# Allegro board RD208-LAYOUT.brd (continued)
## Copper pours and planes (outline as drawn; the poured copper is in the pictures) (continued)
PC_G_V8 on TOP (solid shape): 157.26,98.82 157.8,99.02 158.92,98.73 159.3,98.25 158.92,97.77 157.8,97.48 157.74,97.46 157.68,97.46 157.23,97.73 157.27,98.25
PC_G_V8 on TOP: 157.65,87.35 157.53,87.38 157.43,87.47 157.4,87.6 157.4,90.3 157.43,90.42 157.53,90.52 157.65,90.55 158.65,90.55 158.78,90.58 158.87,90.67 158.9,90.8 158.9,98.55 158.93,98.67 159.03,98.77 159.15,98.8 162.35,98.8 162.46,98.76 162.5,98.65 162.5,87.6 162.47,87.47 162.38,87.38 162.25,87.35
PC_G_W1 on TOP (solid shape): 196.08,75.6 196.5,75.6 196.5,75.2 196.08,75.2 196.08,71.67 195.23,71.67 195.23,72.72 194.81,72.72 194.81,71.67 193.96,71.67 193.96,72.72 193.54,72.72 193.54,71.67 192.69,71.67 192.69,72.72 192.27,72.72 192.27,71.67 191.42,71.67 191.42,75.2 191,75.2 191,75.6 191.42,75.6 191.42,76.47 196.08,76.47
PC_G_W1 on TOP (solid shape): 186.2,69.6 186.35,69.25 186.33,69.12 186.28,68.99 185.69,67.99 185.17,67.76 184.77,68.17 184.36,68.57 184.59,69.09 185.72,69.73 185.85,69.75
PC_G_W1 on TOP: 199.3,65.5 199.24,65.51 199.13,65.57 196.57,68.13 196.46,68.19 196.4,68.2 192.95,68.2 192.82,68.23 192.73,68.33 192.7,68.45 192.7,69.38 192.67,69.5 192.57,69.59 192.45,69.62 191.75,69.62 191.64,69.67 191.6,69.78 191.6,76.2 191.63,76.33 191.72,76.42 191.85,76.45 195.8,76.45 195.86,76.44 195.97,76.38 199.41,72.94 199.44,72.9 199.45,72.84 199.45,72.55 199.52,72.37 199.7,72.3 203.85,72.3 203.96,72.26 204,72.15 204,65.65 203.96,65.54 203.85,65.5
PC_G_W2 on TOP (solid shape): 196.08,84.85 196.5,84.85 196.5,84.45 196.08,84.45 196.08,80.92 195.23,80.92 195.23,81.97 194.81,81.97 194.81,80.92 193.96,80.92 193.96,81.97 193.54,81.97 193.54,80.92 192.69,80.92 192.69,81.97 192.27,81.97 192.27,80.92 191.42,80.92 191.42,84.45 191,84.45 191,84.85 191.42,84.85 191.42,85.72 196.08,85.72
PC_G_W2 on TOP (solid shape): 186.2,78.85 186.35,78.5 186.33,78.37 186.28,78.24 185.69,77.24 185.17,77.01 184.77,77.42 184.36,77.82 184.59,78.34 185.72,78.98 185.85,79
PC_G_W2 on TOP: 198.7,76.25 198.64,76.26 198.53,76.32 197.47,77.38 197.36,77.44 197.3,77.45 192.95,77.45 192.82,77.48 192.73,77.58 192.7,77.7 192.7,78.62 192.67,78.75 192.57,78.84 192.45,78.88 191.75,78.88 191.64,78.92 191.6,79.03 191.6,85.45 191.63,85.58 191.72,85.67 191.85,85.7 195.8,85.7 195.86,85.69 195.97,85.63 196,85.6 198.25,85.6 198.31,85.59 198.42,85.53 199.38,84.57 199.42,84.52 199.45,84.4 199.45,83.3 199.52,83.12 199.7,83.05 203.85,83.05 203.96,83.01 204,82.9 204,76.4 203.96,76.29 203.85,76.25
PC_G_W3 on TOP (solid shape): 196.08,94.1 196.5,94.1 196.5,93.7 196.08,93.7 196.08,90.17 195.23,90.17 195.23,91.22 194.81,91.22 194.81,90.17 193.96,90.17 193.96,91.22 193.54,91.22 193.54,90.17 192.69,90.17 192.69,91.22 192.27,91.22 192.27,90.17 191.42,90.17 191.42,93.7 191,93.7 191,94.1 191.42,94.1 191.42,94.97 196.08,94.97
PC_G_W3 on TOP (solid shape): 186.2,88.1 186.35,87.75 186.33,87.62 186.28,87.49 185.69,86.49 185.17,86.26 184.77,86.67 184.36,87.07 184.59,87.59 185.72,88.23 185.85,88.25
PC_G_W3 on TOP: 192.95,86.7 192.82,86.73 192.73,86.83 192.7,86.95 192.7,87.88 192.67,88 192.57,88.09 192.45,88.12 191.75,88.12 191.64,88.17 191.6,88.28 191.6,94.7 191.63,94.83 191.72,94.92 191.85,94.95 195.65,94.95 195.78,94.92 195.87,94.83 195.9,94.7 195.9,94.05 195.93,93.92 196.03,93.83 196.15,93.8 203.85,93.8 203.96,93.76 204,93.65 204,87.15 203.96,87.04 203.85,87 196.1,87 195.95,86.95 195.8,86.73 195.71,86.7
PC_G_W5 on TOP (solid shape): 196.08,116.2 196.5,116.2 196.5,115.8 196.08,115.8 196.08,112.28 195.23,112.28 195.23,113.33 194.81,113.33 194.81,112.28 193.96,112.28 193.96,113.33 193.54,113.33 193.54,112.28 192.69,112.28 192.69,113.33 192.27,113.33 192.27,112.28 191.42,112.28 191.42,115.8 191,115.8 191,116.2 191.42,116.2 191.42,117.08 196.08,117.08
PC_G_W5 on TOP (solid shape): 186.2,110.2 186.35,109.85 186.33,109.72 186.28,109.59 185.69,108.59 185.17,108.36 184.77,108.77 184.36,109.17 184.59,109.69 185.72,110.33 185.85,110.35
PC_G_W5 on TOP: 196.95,108.4 196.89,108.41 196.78,108.47 196.52,108.73 196.41,108.79 196.35,108.8 192.95,108.8 192.82,108.83 192.73,108.92 192.7,109.05 192.7,109.97 192.67,110.1 192.57,110.19 192.45,110.22 191.75,110.22 191.64,110.27 191.6,110.38 191.6,116.8 191.63,116.92 191.72,117.02 191.85,117.05 199,117.05 199.12,117.02 199.22,116.92 199.25,116.8 199.25,112.45 199.34,112.24 199.55,112.15 200.2,112.15 200.31,112.11 200.35,112 200.35,108.65 200.32,108.53 200.22,108.43 200.1,108.4
PC_G_W6 on TOP (solid shape): 196.08,125.45 196.5,125.45 196.5,125.05 196.08,125.05 196.08,121.53 195.23,121.53 195.23,122.58 194.81,122.58 194.81,121.53 193.96,121.53 193.96,122.58 193.54,122.58 193.54,121.53 192.69,121.53 192.69,122.58 192.27,122.58 192.27,121.53 191.42,121.53 191.42,125.05 191,125.05 191,125.45 191.42,125.45 191.42,126.33 196.08,126.33
PC_G_W6 on TOP (solid shape): 186.2,119.45 186.35,119.1 186.33,118.97 186.28,118.84 185.69,117.84 185.17,117.61 184.77,118.02 184.36,118.42 184.59,118.94 185.72,119.58 185.85,119.6
PC_G_W6 on TOP: 192.95,118.05 192.82,118.08 192.73,118.17 192.7,118.3 192.7,119.22 192.67,119.35 192.57,119.44 192.45,119.47 191.75,119.47 191.64,119.52 191.6,119.62 191.6,126.05 191.63,126.17 191.72,126.27 191.85,126.3 199,126.3 199.12,126.27 199.22,126.17 199.25,126.05 199.25,123.2 199.34,122.99 199.55,122.9 200.2,122.9 200.31,122.86 200.35,122.75 200.35,118.3 200.32,118.17 200.22,118.08 200.1,118.05
PC_G_W7 on TOP (solid shape): 196.08,134.7 196.5,134.7 196.5,134.3 196.08,134.3 196.08,130.78 195.23,130.78 195.23,131.82 194.81,131.82 194.81,130.78 193.96,130.78 193.96,131.82 193.54,131.82 193.54,130.78 192.69,130.78 192.69,131.82 192.27,131.82 192.27,130.78 191.42,130.78 191.42,134.3 191,134.3 191,134.7 191.42,134.7 191.42,135.57 196.08,135.57
PC_G_W7 on TOP (solid shape): 186.2,128.7 186.35,128.35 186.33,128.22 186.28,128.09 185.69,127.09 185.17,126.86 184.77,127.27 184.36,127.67 184.59,128.19 185.72,128.83 185.85,128.85
PC_G_W7 on TOP: 192.95,127.3 192.82,127.33 192.73,127.42 192.7,127.55 192.7,128.5 192.67,128.62 192.57,128.72 192.45,128.75 191.85,128.75 191.72,128.78 191.63,128.88 191.6,129 191.6,135.3 191.63,135.43 191.72,135.52 191.85,135.55 199,135.55 199.12,135.52 199.22,135.43 199.25,135.3 199.25,133.95 199.34,133.74 199.55,133.65 200.2,133.65 200.31,133.61 200.35,133.5 200.35,130.05 200.31,129.94 200.2,129.9 199.2,129.9 199.08,129.87 199.03,129.83 196.57,127.37 196.52,127.33 196.4,127.3
PC_G_W8 on TOP (solid shape): 185.31,138.35 185.48,138.07 185.77,136.95 185.57,136.41 185,136.42 184.43,136.41 184.23,136.95 184.52,138.07 184.69,138.35 185,138.45
PC_G_W8 on TOP: 193.15,136.55 193.03,136.58 192.93,136.68 192.9,136.8 192.9,137.8 192.87,137.93 192.78,138.02 192.65,138.05 184.7,138.05 184.57,138.08 184.48,138.18 184.45,138.3 184.45,141.5 184.49,141.61 184.6,141.65 195.65,141.65 195.78,141.62 195.87,141.53 195.9,141.4 195.9,136.8 195.87,136.68 195.78,136.58 195.65,136.55
TRANS2_AUX on BOTTOM (solid shape): 197.03,10.28 197.5,10.6 197.97,10.28 198.52,8.85 198.24,8.2 197.59,8.49 197.58,8.53 197.42,8.53 197.41,8.49 196.76,8.2 196.48,8.85
TRANS2_PRI on BOTTOM (solid shape): 188.82,17.45 189.25,17.45 189.25,17.05 188.82,17.05 188.82,15.8 188.68,15.8 188.68,15.5 188.28,15.5 188.28,15.8 188.03,15.8 188.03,15.5 187.62,15.5 187.62,15.8 187.38,15.8 187.38,15.5 186.97,15.5 186.97,15.8 186.72,15.8 186.72,15.5 186.32,15.5 186.32,15.8 186.18,15.8 186.18,17.05 185.75,17.05 185.75,17.45 186.18,17.45 186.18,18 188.82,18
TRANS2_PRI on BOTTOM: 187.1,7.25 187.04,7.26 186.93,7.32 186.32,7.93 186.28,7.98 186.25,8.1 186.25,17.75 186.28,17.88 186.38,17.97 186.5,18 188.5,18 188.62,17.97 188.72,17.88 188.75,17.75 188.75,8.1 188.74,8.04 188.68,7.93 188.07,7.32 188.02,7.28 187.9,7.25
TRANS2_SEC2 on BOTTOM (solid shape): 202.41,39.8 202.55,39.45 202.52,39.27 202.43,39.12 202.4,39.08 202.47,38.95 202.51,38.95 203.06,38.5 202.61,37.96 201.08,37.8 200.58,38.07 200.66,38.63 201.68,39.78 201.85,39.9 202.05,39.95
TRANS2_SEC3 on BOTTOM (solid shape): 217.41,39.8 217.55,39.45 217.52,39.27 217.43,39.12 217.4,39.08 217.47,38.95 217.51,38.95 218.06,38.5 217.61,37.96 216.08,37.8 215.58,38.07 215.66,38.63 216.68,39.78 216.85,39.9 217.05,39.95
TRANS2_SEC4 on BOTTOM (solid shape): 217.03,10.28 217.5,10.6 217.97,10.28 218.52,8.85 218.24,8.2 217.59,8.49 217.58,8.53 217.42,8.53 217.41,8.49 216.76,8.2 216.48,8.85
V_UL on TOP (solid shape): 48.77,99.08 49.19,99.08 49.19,100.12 50.04,100.12 50.04,99.08 50.46,99.08 50.46,100.12 51.31,100.12 51.31,99.08 51.73,99.08 51.73,100.12 52.58,100.12 52.58,96.6 53.01,96.6 53.01,96.2 52.58,96.2 52.58,95.33 47.92,95.33 47.92,96.2 47.49,96.2 47.49,96.6 47.92,96.6 47.92,100.12 48.77,100.12
V_UL on TOP (solid shape): 59.06,107.53 59.23,107.23 59.64,106.83 59.41,106.31 58.41,105.72 57.8,105.8 57.72,106.41 58.31,107.41 58.49,107.59 58.74,107.65
V_UL on BOTTOM (solid shape): 190.88,40.02 190.98,40.57 191.53,40.67 192.94,40.06 193.16,39.87 193.24,39.6 193.09,39.25 192.74,39.1 192.64,39.11 192.54,39.14 192.5,39.16 192.39,39.05 192.41,39.01 192.15,38.35 191.49,38.61
V_UL on TOP: 48.35,95.35 48.23,95.38 48.13,95.47 48.1,95.6 48.1,95.65 48.1,95.7 48.1,98.5 48.06,98.62 47.97,98.72 47.85,98.75 39.35,98.75 39.23,98.78 39.13,98.88 39.1,99 39.1,105.9 39.13,106.03 39.23,106.12 39.35,106.15 47.9,106.15 48.02,106.18 48.12,106.28 48.15,106.4 48.15,106.95 48.18,107.08 48.27,107.17 48.4,107.2 51.05,107.2 51.17,107.17 51.27,107.08 51.3,106.95 51.3,106 51.33,105.88 51.42,105.78 51.55,105.75 52.15,105.75 52.27,105.72 52.37,105.62 52.4,105.5 52.4,95.6 52.37,95.47 52.27,95.38 52.15,95.35
V_VL on TOP (solid shape): 127.8,91.83 128.68,91.83 128.68,87.17 127.8,87.17 127.8,86.75 127.4,86.75 127.4,87.17 123.88,87.17 123.88,88.02 124.92,88.02 124.92,88.44 123.88,88.44 123.88,89.29 124.92,89.29 124.92,89.71 123.88,89.71 123.88,90.56 124.92,90.56 124.92,90.98 123.88,90.98 123.88,91.83 127.4,91.83 127.4,92.25 127.8,92.25
V_VL on TOP (solid shape): 117.17,98.89 117.69,98.66 118.33,97.53 118.35,97.4 118.2,97.05 117.85,96.9 117.72,96.92 117.59,96.97 116.59,97.56 116.36,98.08 116.77,98.48
V_VL on BOTTOM (solid shape): 207.03,40.88 207.5,41.2 207.97,40.88 208.52,39.45 208.24,38.8 207.59,39.09 207.58,39.13 207.42,39.13 207.41,39.09 206.76,38.8 206.48,39.45
V_VL on TOP: 118.1,78.25 117.97,78.28 117.88,78.38 117.85,78.5 117.85,86.95 117.82,87.08 117.72,87.17 117.6,87.2 117.05,87.2 116.92,87.23 116.83,87.33 116.8,87.45 116.8,90.3 116.83,90.42 116.92,90.52 117.05,90.55 117.97,90.55 118.1,90.58 118.19,90.67 118.22,90.8 118.22,91.5 118.27,91.61 118.38,91.65 128.4,91.65 128.53,91.62 128.62,91.53 128.65,91.4 128.65,87.6 128.62,87.47 128.53,87.38 128.4,87.35 128.3,87.35 126.5,87.35 126.38,87.31 126.28,87.22 126.25,87.1 126.25,79.35 126.24,79.29 126.18,79.18 125.32,78.32 125.27,78.28 125.15,78.25
V_WL on TOP (solid shape): 196.08,106.95 196.5,106.95 196.5,106.55 196.08,106.55 196.08,103.03 195.23,103.03 195.23,104.08 194.81,104.08 194.81,103.03 193.96,103.03 193.96,104.08 193.54,104.08 193.54,103.03 192.69,103.03 192.69,104.08 192.27,104.08 192.27,103.03 191.42,103.03 191.42,106.55 191,106.55 191,106.95 191.42,106.95 191.42,107.83 196.08,107.83
V_WL on TOP (solid shape): 186.2,97.35 186.35,97 186.33,96.87 186.28,96.74 185.69,95.74 185.17,95.51 184.77,95.92 184.36,96.32 184.59,96.84 185.72,97.48 185.85,97.5
V_WL on BOTTOM (solid shape): 222.03,40.88 222.5,41.2 222.97,40.88 223.52,39.45 223.24,38.8 222.59,39.09 222.58,39.13 222.42,39.13 222.41,39.09 221.76,38.8 221.48,39.45
V_WL on TOP: 192.95,95.95 192.82,95.98 192.73,96.08 192.7,96.2 192.7,97.12 192.67,97.25 192.57,97.34 192.45,97.38 191.75,97.38 191.64,97.42 191.6,97.53 191.6,107.55 191.63,107.67 191.72,107.77 191.85,107.8 195.65,107.8 195.78,107.77 195.87,107.67 195.9,107.55 195.9,107.45 195.9,105.5 195.94,105.38 196.03,105.28 196.15,105.25 201.5,105.25 201.56,105.24 201.67,105.18 202.38,104.47 202.49,104.41 202.55,104.4 204.5,104.4 204.62,104.37 204.72,104.28 204.75,104.15 204.75,97.25 204.72,97.12 204.62,97.03 204.5,97 196.2,97 196.07,96.97 195.98,96.88 195.95,96.75 195.95,96.2 195.92,96.08 195.82,95.98 195.7,95.95
VP_1R8_CPLD_D on TOP (solid shape): 82.77,117.33 82.89,117.05 82.85,116.89 82.75,116.75 83.17,116.37 82.79,115.95 81.66,115.9 81.27,116.15 81.37,116.6 82.22,117.35 82.34,117.42 82.48,117.45
VP_1R8_CPLD_D on CONDUCTIVE3 (solid shape): 82.92,117.39 83.44,117.16 84.08,116.03 84.1,115.9 83.95,115.55 83.6,115.4 83.47,115.42 83.34,115.47 82.34,116.06 82.11,116.58 82.52,116.98
VP_3R3_PRH_D on TOP (solid shape): 92.27,117.33 92.39,117.05 92.35,116.89 92.25,116.75 92.67,116.37 92.29,115.95 91.16,115.9 90.77,116.15 90.87,116.6 91.72,117.35 91.84,117.42 91.98,117.45
VP_3R3_PRH_D on CONDUCTIVE4 (solid shape): 91.91,117.32 92.45,117.52 93.58,117.23 93.95,116.75 93.57,116.27 92.45,115.98 92.39,115.96 92.33,115.96 91.88,116.23 91.92,116.75
VP_3R3_PRH_D on CONDUCTIVE4 (solid shape): 92.56,118.35 92.73,118.08 93.02,116.95 92.82,116.41 92.25,116.42 91.68,116.41 91.48,116.95 91.77,118.08 91.94,118.35 92.25,118.45
VP_3R3_PRH_D on CONDUCTIVE4: 108.7,115.85 108.63,115.88 108.6,115.95 108.6,117.3 108.59,117.38 108.57,117.46 108.53,117.54 108.48,117.62 108.42,117.68 108.34,117.73 108.26,117.77 108.18,117.79 108.1,117.8 107.8,117.8 107.73,117.83 107.7,117.9 107.7,118.3 107.73,118.42 107.83,118.52 107.95,118.55 108.92,118.55 108.95,118.54 108.99,118.52 110.51,117 110.73,116.87 110.86,116.85 111.2,116.85 111.27,116.82 111.3,116.75 111.3,116.1 111.27,115.97 111.17,115.88 111.05,115.85
VP_5R0_PRH_D on CONDUCTIVE3 (solid shape): 76.81,123.16 77.33,123.39 77.73,122.98 78.14,122.58 77.91,122.06 76.91,121.47 76.3,121.55 76.22,122.16
VP_5R0_PRH_D on CONDUCTIVE3 (solid shape): 77.16,123.32 77.7,123.52 78.82,123.23 79.2,122.75 78.82,122.27 77.7,121.98 77.64,121.96 77.58,121.96 77.13,122.23 77.17,122.75
VP_5R0_PRH_D on TOP: 77.65,121.95 77.54,121.99 77.5,122.1 77.5,123.4 77.54,123.51 77.65,123.55 78,123.55 78.3,123.85 78.3,125.25 78.33,125.38 78.42,125.47 78.55,125.5 78.95,125.5 79.08,125.47 79.17,125.38 79.2,125.25 79.2,124.15 79.23,124.03 79.27,123.98 79.43,123.82 79.47,123.77 79.5,123.65 79.5,122.1 79.46,121.99 79.35,121.95
VP_15R0_INV_ISO on BOTTOM: 170.75,30.25 170.62,30.28 170.53,30.38 170.5,30.5 170.5,36.25 170.53,36.38 170.62,36.47 170.75,36.5 172.25,36.5 172.38,36.47 172.47,36.38 172.5,36.25 172.5,30.5 172.47,30.38 172.38,30.28 172.25,30.25
VP_15R0_INV_ISO on BOTTOM: 178.5,3 178.12,3.08 177.79,3.29 176.79,4.29 176.79,5.71 178.21,5.71 178.91,5 191.15,5 191.5,5.35 191.5,8.45 192.5,9.45 193.5,8.45 193.5,3.49 193.49,3.45 193.47,3.42 193.08,3.03 193.05,3.01 193.01,3
VP_15R0_INV_LDO on TOP: 149.15,33.7 149.09,33.71 148.98,33.77 148.57,34.18 148.53,34.23 148.5,34.35 148.5,34.9 148.51,34.96 148.57,35.07 149.68,36.18 149.73,36.22 149.85,36.25 152.85,36.25 152.97,36.22 153.07,36.12 153.1,36 153.1,35.3 153.07,35.17 152.97,35.08 152.85,35.05 150.85,35.05 150.73,35.02 150.68,34.98 150.57,34.87 150.51,34.76 150.5,34.7 150.5,34.35 150.49,34.29 150.43,34.18 150.02,33.77 149.97,33.73 149.85,33.7
VP_15R0_INV_LDO on BOTTOM: 101.5,8 101.38,8.03 101.28,8.12 101.25,8.25 101.25,16.25 101.28,16.38 101.38,16.47 101.5,16.5 115.65,16.5 115.78,16.47 115.87,16.38 115.9,16.25 115.9,9.61 115.89,9.55 115.86,9.51 114.39,8.04 114.35,8.01 114.29,8
VP_15R0_INV_LDO on BOTTOM: 165,30 164.88,30.03 164.78,30.12 164.75,30.25 164.75,32.4 164.76,32.46 164.82,32.57 165.18,32.93 165.23,32.97 165.35,33 166.5,33 166.62,32.97 166.72,32.88 166.75,32.75 166.75,30.25 166.72,30.12 166.62,30.03 166.5,30
VP_400R0_INV on TOP (solid shape): 48.77,139.68 49.19,139.68 49.19,140.72 50.04,140.72 50.04,139.68 50.46,139.68 50.46,140.72 51.31,140.72 51.31,139.68 51.73,139.68 51.73,140.72 52.58,140.72 52.58,137.2 53.01,137.2 53.01,136.8 52.58,136.8 52.58,135.93 47.92,135.93 47.92,136.8 47.49,136.8 47.49,137.2 47.92,137.2 47.92,140.72 48.77,140.72
VP_400R0_INV on TOP (solid shape): 87.2,91.83 88.08,91.83 88.08,87.17 87.2,87.17 87.2,86.75 86.8,86.75 86.8,87.17 83.28,87.17 83.28,88.02 84.33,88.02 84.33,88.44 83.28,88.44 83.28,89.29 84.33,89.29 84.33,89.71 83.28,89.71 83.28,90.56 84.33,90.56 84.33,90.98 83.28,90.98 83.28,91.83 86.8,91.83 86.8,92.25 87.2,92.25
VP_400R0_INV on TOP (solid shape): 196.08,66.35 196.5,66.35 196.5,65.95 196.08,65.95 196.08,62.42 195.23,62.42 195.23,63.48 194.81,63.48 194.81,62.42 193.96,62.42 193.96,63.48 193.54,63.48 193.54,62.42 192.69,62.42 192.69,63.48 192.27,63.48 192.27,62.42 191.42,62.42 191.42,65.95 191,65.95 191,66.35 191.42,66.35 191.42,67.22 196.08,67.22
VP_400R0_INV on TOP: 74.1,77.85 74.04,77.86 73.93,77.92 73.52,78.33 73.48,78.38 73.45,78.5 73.45,88.44 73.46,88.5 73.49,88.54 74.21,89.26 74.25,89.29 74.31,89.3 78.5,89.3 80.57,89.93 81.98,91.67 82.07,91.7 87.8,91.7 87.92,91.67 88.02,91.58 88.05,91.45 88.05,87.85 88.04,87.79 87.98,87.68 85.07,84.77 85.01,84.66 85,84.6 85,78.95 84.99,78.89 84.93,78.78 84.07,77.92 84.02,77.88 83.9,77.85
VP_400R0_INV on TOP: 31.45,20.1 31.39,20.11 31.28,20.17 30.52,20.93 30.41,20.99 30.35,21 21.27,21 21.21,21.01 21.16,21.04 14.95,27.26 14.38,27.73 13.74,28.1 13.05,28.36 12.32,28.48 11.95,28.5 2.15,28.5 2.04,28.54 2,28.65 2,37.25 2.03,37.38 2.12,37.47 2.25,37.5 26.4,37.5 26.46,37.49 26.57,37.43 28.93,35.07 29.04,35.01 29.1,35 40.89,35 40.95,34.99 40.99,34.96 43.01,32.94 43.04,32.9 43.05,32.84 43.05,20.35 43.02,20.23 42.92,20.13 42.8,20.1
VP_400R0_INV on TOP: 48.1,136 48.04,136.01 47.93,136.07 45.07,138.93 44.96,138.99 44.9,139 33.06,139 33,139.01 32.96,139.04 32.04,139.96 32.01,140 32,140.06 32,147.94 32.01,148 32.04,148.04 32.93,148.93 32.98,148.97 33.1,149 50.15,149 50.26,148.96 50.3,148.85 50.3,145 50.87,143.02 52.48,141.6 52.5,141.52 52.5,136.25 52.47,136.12 52.38,136.03 52.25,136
VP_400R0_INV on TOP: 63.5,14.7 63.38,14.73 63.28,14.82 63.25,14.95 63.25,20.9 63.28,21.02 63.38,21.12 63.5,21.15 66.3,21.15 66.42,21.12 66.52,21.02 66.55,20.9 66.55,17.12 65.74,16.03 65.27,14.75 65.16,14.71 65.04,14.7
VP_400R0_INV on TOP: 219.6,62.75 219.66,62.74 219.77,62.68 220.58,61.87 220.62,61.82 220.65,61.7 220.65,53.5 220.64,53.44 220.58,53.33 213.54,46.29 213.5,46.26 213.44,46.25 195.56,46.25 195.5,46.26 195.46,46.29 191.04,50.71 191.01,50.75 191,50.81 191,66.55 191.01,66.61 191.07,66.72 191.43,67.08 191.48,67.12 191.6,67.15 195.9,67.15 195.96,67.14 196.07,67.08 200.33,62.82 200.44,62.76 200.5,62.75 ; 1 cut-out
VP_400R0_INV on BOTTOM: 63.5,14.75 63.38,14.78 63.28,14.88 63.25,15 63.25,18.9 63.28,19.02 63.38,19.12 63.5,19.15 65,19.15 65.12,19.12 65.22,19.02 65.25,18.9 65.25,15 65.22,14.88 65.12,14.78 65,14.75
VP_400R0_INV on BOTTOM: 74.2,77.85 74.08,77.88 73.98,77.97 73.95,78.1 73.95,83.2 73.98,83.33 74.08,83.42 74.2,83.45 82.9,83.45 83.03,83.42 83.12,83.33 83.15,83.2 83.15,78.1 83.12,77.97 83.03,77.88 82.9,77.85
VP_400R0_INV on BOTTOM: 213.93,55.5 213.87,55.51 213.82,55.54 207.84,61.52 207.81,61.57 207.8,61.63 207.8,62.5 207.83,62.62 207.93,62.72 208.05,62.75 219.95,62.75 220.01,62.74 220.12,62.68 220.53,62.27 220.57,62.22 220.6,62.1 220.6,55.75 220.57,55.62 220.47,55.53 220.35,55.5
VP_400R0_INV on BOTTOM: 32.85,22.7 32.79,22.71 32.68,22.77 32.52,22.93 32.48,22.98 32.45,23.1 32.45,25.5 32.42,25.62 32.38,25.67 32.07,25.98 31.96,26.04 31.9,26.05 27.31,26.05 27.25,26.06 27.21,26.09 26.75,26.55 24.96,26.55 24.9,26.56 24.86,26.59 24.44,27.01 24.41,27.05 24.4,27.11 24.4,34.75 24.43,34.88 24.52,34.97 24.65,35 40.9,35 41.01,34.96 41.05,34.85 41.05,22.85 41.01,22.74 40.9,22.7
VP_400R0_INV on BOTTOM: 32.65,140.6 32.52,140.63 32.43,140.72 32.4,140.85 32.4,145.95 32.43,146.07 32.52,146.17 32.65,146.2 41.35,146.2 41.48,146.17 41.57,146.07 41.6,145.95 41.6,140.85 41.57,140.72 41.48,140.63 41.35,140.6
VP_400R0_INV on CONDUCTIVE3: outline of 197 points within 1,14.35 239,149 ; 1 cut-out
N3161846 on BOTTOM: 186.6,18.6 186.47,18.63 186.38,18.73 186.35,18.85 186.35,20.25 186.38,20.38 186.47,20.47 186.6,20.5 188.5,20.5 188.62,20.47 188.72,20.38 188.75,20.25 188.75,19.75 188.72,19.62 188.62,19.53 188.5,19.5 188.25,19.5 188.12,19.47 188.03,19.38 188,19.25 188,18.85 187.97,18.73 187.88,18.63 187.75,18.6
N16128748 on BOTTOM: 95.1,8.75 95.04,8.76 94.93,8.82 94.57,9.18 94.53,9.23 94.5,9.35 94.5,14.15 94.51,14.21 94.57,14.32 94.93,14.68 94.98,14.72 95.1,14.75 99.45,14.75 99.51,14.74 99.62,14.68 100.23,14.07 100.27,14.02 100.3,13.9 100.3,9.6 100.29,9.54 100.23,9.43 99.62,8.82 99.57,8.78 99.45,8.75

Small or netless copper shapes (teardrops, artwork), in the pictures only: 207 on TOP, 181 on BOTTOM, 4 on CONDUCTIVE2, 5 on CONDUCTIVE3, 8 on CONDUCTIVE4, 4 on CONDUCTIVE5

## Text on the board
PAGE_OUTLINE: C14 | R312 | K | R2 | C4 | 1 | 8 | C5 | D1 | A | 5 | 4 | D57 | D54 | D52 | D53 | D55 | D56 | D50 | D51 | TP25 | TP65 | U1- | TP26 | U2+ | TP66 | U3+ | TP28 | U4+ | TP29 | U5+ | TP30 | TP70 | TP31 | U7+ | TP71 | U7- | TP32 | U8+ | TP72 | U8- | U1+ | U2- | TP27 | TP67 | U3- | TP68 | U4- | TP69 | U5- | U6+ | U6- | R298 | R299 | 6 | 2 | R258 | ON | R168 | R222 | 14 | 13 | R211 | R260 | R213 | R212 | R210 | C35 | R169 | 7 | 12 | R223 | 50 | R262 | C34 | R170 | R224 | TP16 | R266 | 26 | R171 | C42 | TP14 | R225 | TP9 | R48 | R49 | R50 | R51 | R52 | R53 | R54 | R55 | R79 | R74 | C46 | IC22 | TP13 | R209 | R264 | R66 | R67 | R68 | R69 | R70 | R71 | R72 | R73 | C39 | R172 | R226 | C44 | IC8 | IC6 | R268 | C43 | R40 | R41 | R42 | R43 | R44 | R45 | R46 | R47 | C38 | R173 | R227 | R58 | R59 | R60 | R61 | R62 | R63 | R64 | R65 | 39 | 40 | R270 | C100 | R142 | C136 | R143 | R174 | R228 | CN3 | C135 | C101 | R140 | C94 | C95 | IC16 | R139 | C98 | C99 | R272 | C93 | R175 | C92 | IC17 | C97 | C134 | R137 | R229 | C45 | C91 | C90 | IC14 | C133 | R192 | C96 | R136 | TP88 | TP86 | TP85 | TP84 | TP60 | W4+ | TP83 | TP59 | TP82 | TP58 | W8- | TP64 | W8+ | TP87 | TP63 | W7+ | TP62 | W6+ | TP61 | W4- | W3+ | W2- | W2+ | TP81 | W7- | W6- | W5+ | W3- | W1- | W5- | TP57 | W1+ | 16 | D68 | D69 | D73 | D72 | D71 | D70 | D67 | D66 | 9 | R246 | R247 | R255 | R220 | R245 | R249 | R251 | R253 | R257 | R214 | R215 | R218 | R219 | R216 | R221 | R217 | R179 | R183 | R176 | R177 | R181 | R182 | R178 | R180 | TP41 | D58 | V1+ | R148 | DS4 | TP73 | R149 | R147 | DS3 | V1- | R150 | R146 | DS2 | TP42 | R145 | R151 | DS1 | D59 | V2+ | R152 | C31 | C40 | TP74 | C41 | 75 | V2- | TP43 | D60 | R78 | V3+ | 76 | R77 | TP75 | V3- | R75 | R76 | TP44 | D62 | V4+ | TP15 | TP76 | 100 | V4- | C33 | C32 | TP10 | TP45 | D61 | V5+ | TP11 | TP12 | R153 | C102 | TP77 | V5- | TP46 | D63 | V6+ | TP78 | V6- | TP47 | D64 | R133 | R131 | R129 | V7+ | R135 | R134 | IC21 | R128 | R132 | TP79 | IC18 | R130 | V7- | TP48 | D65 | V8+ | R57 | R311 | C141 | R240 | IC15 | TP80 | R239 | V8- | R56 | C140 | R310 | R159 | IC13 | R158 | R157 | R238 | R198 | C139 | R156 | R144 | R309 | IC20 | R141 | IC19 | R138 | IC9 | R187 | R190 | R189 | R188 | R185 | R191 | R186 | R184 | R230 | R237 | R234 | R233 | R232 | R231 | R236 | R235 | R284 | R278 | R276 | R288 | R286 | R282 | R280 | R274 | GND D | C48 | C49 | C54 | C56 | TP1 | DC+ | TP2 | D21 | D23 | D25 | D17 | D15 | D19 | DC-(GND) | R4 | IC1 | R12 | R6 | R14 | R13 | Q1 | R17 | R16 | C10 | C12 | TP18 | TP20 | TP17 | U1 | U2 | TP19 | U4 | TP23 | TP24 | U8 | U3 | TP22 | U6 | U7 | TP21 | U5 | C61 | +5V | CN2 | R39 | TP6 | 5V | RV1 | C23 | C24 | IC5 | C27 | T3 | C29 | TP8 | D13 | 1.8V | R36 | S1 | Q19 | IC4 | C63 | C28 | CN4 | TP7 | 3.3V | Q21 | IC7 | Q23 | C65 | C36 | Q25 | C37 | Q27 | S2 | V6 | TP38 | Q29 | C69 | PS15V | Q31 | TP3 | R22 | CN5 | Q33 | IC2 | C71 | R26 | R292 | IC11 | R291 | TP4 | LDO15V | TP5 | 15V | C89 | TP56 | W8 | TP49 | TP52 | TP55 | TP54 | TP50 | W7 | W6 | TP53 | W5 | TP51 | W4 | W1 | W3 | W2 | Q47 | Q45 | Q43 | Q37 | Q49 | Q41 | Q39 | Q35 | T2 | CN1 | C66 | C67 | C1 | C2 | C3 | Q15 | Q17 | Q11 | Q9 | Q3 | Q7 | Q13 | Q5 | R207 | C13 | R18 | R19 | IC10 | D4 | D6 | R290 | R289 | FL1 | C30 | D27 | TP33 | V1 | C25 | D29 | TP34 | V2 | TP35 | D31 | V3 | TP36 | V4 | C7 | TP37 | D33 | V5 | D35 | TP39 | V7 | D37 | C15 | R295 | TP40 | V8 | C75 | C16 | R296 | R27 | R24 | R293 | R294 | IC12 | D41 | D43 | D39 | D49 | D45 | D47 | C78 | C80 | C82 | C84 | MULTI-LEVEL INVERTER | U | V | W
SYMBOL-1-BOTTOM: A | K | R316 | R81 | R85 | R87 | R83 | R314 | R315 | R313 | R93 | R91 | Q14 | R317 | Q12 | R318 | R89 | Q16 | R95 | R319 | R320 | Q18 | C150 | R345 | R346 | C151 | R347 | C152 | R348 | C153 | R105 | Q28 | R349 | C154 | R107 | Q30 | R350 | C155 | R109 | Q32 | R351 | C156 | R111 | Q34 | R352 | C157 | Q48 | R333 | Q44 | Q50 | Q46 | R334 | R336 | R335 | R125 | R121 | R127 | R123 | 8 | 1 | 5 | R339 | R337 | R338 | R340 | Q10 | Q4 | Q6 | Q8 | C142 | C145 | C143 | C144 | R342 | R343 | R341 | R344 | C147 | C148 | C146 | C149 | R97 | Q20 | R321 | R99 | Q22 | R322 | R100 | Q24 | R323 | R102 | Q26 | R324 | R325 | R326 | R327 | R328 | Q42 | C161 | R119 | Q40 | C160 | R117 | R332 | R356 | R331 | R355 | R113 | Q38 | C159 | R115 | Q36 | C158 | R330 | R354 | R329 | R353 | C165 | C164 | C163 | C162 | R357 | R359 | R360 | R358 | R196 | R194 | R195 | R193 | R1 | D20 | D24 | D22 | D18 | D16 | R80 | PC4 | PC5 | PC6 | PC7 | PC8 | PC1 | PC2 | PC3 | C104 | D26 | C62 | R199 | R98 | C64 | C105 | R101 | D2 | C106 | C68 | R200 | R103 | C70 | C107 | R104 | C72 | C108 | R243 | R106 | R241 | R242 | R244 | C109 | C73 | R201 | R108 | C74 | C110 | R110 | R202 | C76 | C111 | R21 | R20 | R25 | R23 | R155 | PC21 | PC24 | PC23 | PC22 | PC20 | PC19 | PC17 | PC18 | C17 | D7 | C103 | R33 | Q2 | C128 | C138 | C137 | C22 | R197 | R34 | R32 | R28 | D48 | R29 | D40 | D42 | D46 | D38 | R300 | R31 | C21 | C18 | C19 | C130 | R9 | R5 | R10 | C11 | R15 | D14 | R11 | R7 | R3 | C58 | C57 | C53 | C59 | C50 | C8 | C117 | C114 | C116 | C113 | C118 | R86 | R94 | C47 | C60 | C55 | R82 | R88 | R90 | R84 | R92 | C112 | C119 | C115 | R96 | PC9 | D28 | PC10 | D30 | C6 | C9 | C131 | PC11 | C132 | R8 | PC12 | D3 | D32 | PC13 | D34 | PC14 | D36 | PC15 | R167 | PC16 | R166 | R165 | R297 | R164 | R163 | R162 | R161 | R160 | R302 | R301 | R30 | C129 | C124 | C122 | C127 | C123 | R124 | R122 | R116 | R114 | R112 | C85 | C83 | C88 | IC3 | R126 | R118 | R120 | C81 | C121 | C120 | C126 | C125 | R154 | C79 | C87 | C86 | C77 | R208 | R304 | D44 | D8 | D10 | R303 | D9 | R306 | R305 | D11 | C20 | R203 | R205 | R204 | R206 | R307 | R308
